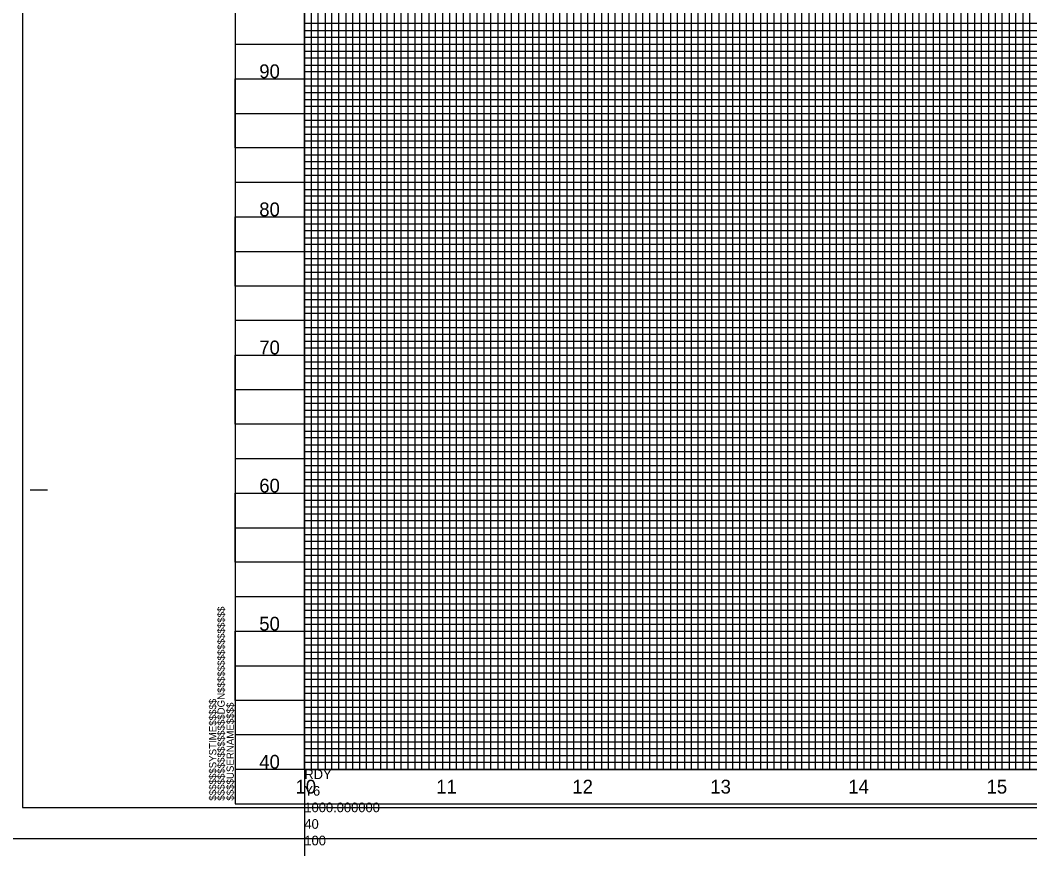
# Model space of a CAD drawing. Extents: x 2345490 to 2436403, y 465165 to 573888.
# Drawn here: x 2381561 to 2382292, y 548918 to 549518 of the extents above; entities that cross this region are included whole.
import ezdxf

# ---------------------------------------------------------------- set-up
doc = ezdxf.new("R2010")
doc.units = 0
for name, color, linetype in [('Old_Level_18', 7, 'Continuous'), ('Old_Level_40', 7, 'Continuous'), ('Old_Level_41', 7, 'Continuous'), ('Old_Level_42', 7, 'Continuous'), ('Old_Level_43', 7, 'Continuous'), ('Old_Level_50', 7, 'Continuous'), ('Old_Level_51', 7, 'Continuous'), ('Old_Level_52', 7, 'Continuous'), ('Old_Level_62', 7, 'Continuous'), ('Old_Level_63', 7, 'Continuous')]:
    doc.layers.add(name, color=color, linetype=linetype)

msp = doc.modelspace()

# ---------------------------------------------------------------- linework, layer by layer
at = {"layer": 'Old_Level_18'}
msp.add_line((2381716.79875, 548950.3665), (2381716.79875, 548950.3665), dxfattribs=at)
msp.add_line((2381716.79875, 548950.3665), (2381716.79875, 548950.3665), dxfattribs=at)
msp.add_lwpolyline([(2383216.79875, 550000.3665), (2381716.79875, 550000.3665), (2381716.79875, 548950.3665), (2383216.79875, 548950.3665)], close=True, dxfattribs=at)
at = {"layer": 'Old_Level_40'}
msp.add_line((2381716.79875, 548950.3665), (2381716.79875, 548950.3665), dxfattribs=at)
msp.add_line((2381716.79875, 548950.3665), (2381716.79875, 548950.3665), dxfattribs=at)
msp.add_line((2381716.79875, 548950.3665), (2381716.79875, 548950.3665), dxfattribs=at)
msp.add_line((2381716.79875, 548950.3665), (2381716.79875, 548950.3665), dxfattribs=at)
at = {"layer": 'Old_Level_41'}
for p, q in [((2381568.29875, 549177.8665), (2381580.79875, 549177.8665)), ((2383216.79875, 548975.3665), (2381716.79875, 548975.3665))]:
    msp.add_line(p, q, dxfattribs=at)
for points in [[(2381716.79875, 550000.3665), (2381766.79875, 550000.3665), (2381766.79875, 548975.3665), (2381816.79875, 548975.3665), (2381816.79875, 550000.3665), (2381866.79875, 550000.3665), (2381866.79875, 548975.3665), (2381916.79875, 548975.3665), (2381916.79875, 550000.3665), (2381966.79875, 550000.3665), (2381966.79875, 548975.3665), (2382016.79875, 548975.3665), (2382016.79875, 550000.3665), (2382066.79875, 550000.3665), (2382066.79875, 548975.3665), (2382116.79875, 548975.3665), (2382116.79875, 550000.3665), (2382166.79875, 550000.3665), (2382166.79875, 548975.3665), (2382216.79875, 548975.3665), (2382216.79875, 550000.3665), (2382266.79875, 550000.3665), (2382266.79875, 548975.3665), (2382316.79875, 548975.3665)], [(2381791.79875, 548975.3665), (2381791.79875, 550000.3665), (2381841.79875, 550000.3665), (2381841.79875, 548975.3665), (2381891.79875, 548975.3665), (2381891.79875, 550000.3665), (2381941.79875, 550000.3665), (2381941.79875, 548975.3665), (2381991.79875, 548975.3665), (2381991.79875, 550000.3665), (2382041.79875, 550000.3665), (2382041.79875, 548975.3665), (2382091.79875, 548975.3665), (2382091.79875, 550000.3665), (2382141.79875, 550000.3665), (2382141.79875, 548975.3665), (2382191.79875, 548975.3665), (2382191.79875, 550000.3665), (2382241.79875, 550000.3665), (2382241.79875, 548975.3665), (2382291.79875, 548975.3665), (2382291.79875, 550000.3665), (2382341.79875, 550000.3665)], [(2383216.79875, 549500.3665), (2381716.79875, 549500.3665), (2381716.79875, 549450.3665), (2383216.79875, 549450.3665)], [(2383216.79875, 549400.3665), (2381716.79875, 549400.3665), (2381716.79875, 549350.3665), (2383216.79875, 549350.3665)], [(2383216.79875, 549325.3665), (2381716.79875, 549325.3665), (2381716.79875, 549375.3665), (2383216.79875, 549375.3665)], [(2383216.79875, 549300.3665), (2381716.79875, 549300.3665), (2381716.79875, 549250.3665), (2383216.79875, 549250.3665)], [(2383216.79875, 549225.3665), (2381716.79875, 549225.3665), (2381716.79875, 549275.3665), (2383216.79875, 549275.3665)], [(2383216.79875, 549200.3665), (2381716.79875, 549200.3665), (2381716.79875, 549150.3665), (2383216.79875, 549150.3665)], [(2383216.79875, 549100.3665), (2381716.79875, 549100.3665), (2381716.79875, 549050.3665), (2383216.79875, 549050.3665)], [(2383216.79875, 549025.3665), (2381716.79875, 549025.3665), (2381716.79875, 549075.3665), (2383216.79875, 549075.3665)], [(2383216.79875, 549000.3665), (2381716.79875, 549000.3665)], [(2381754.29875, 548950.3665), (2381754.29875, 548950.3665)]]:
    msp.add_lwpolyline(points, dxfattribs=at)
at = {"layer": 'Old_Level_42'}
for points in [[(2383216.79875, 549425.3665), (2381716.79875, 549425.3665), (2381716.79875, 549475.3665), (2383216.79875, 549475.3665)], [(2383216.79875, 549125.3665), (2381716.79875, 549125.3665), (2381716.79875, 549175.3665), (2383216.79875, 549175.3665)]]:
    msp.add_lwpolyline(points, dxfattribs=at)
at = {"layer": 'Old_Level_43'}
for points in [[(2381771.79875, 550000.3665), (2381771.79875, 548975.3665), (2381776.79875, 548975.3665), (2381776.79875, 550000.3665)], [(2381781.79875, 550000.3665), (2381781.79875, 548975.3665), (2381786.79875, 548975.3665), (2381786.79875, 550000.3665)], [(2381796.79875, 550000.3665), (2381796.79875, 548975.3665), (2381801.79875, 548975.3665), (2381801.79875, 550000.3665)], [(2381806.79875, 550000.3665), (2381806.79875, 548975.3665), (2381811.79875, 548975.3665), (2381811.79875, 550000.3665)], [(2381821.79875, 550000.3665), (2381821.79875, 548975.3665), (2381826.79875, 548975.3665), (2381826.79875, 550000.3665)], [(2381831.79875, 550000.3665), (2381831.79875, 548975.3665), (2381836.79875, 548975.3665), (2381836.79875, 550000.3665)], [(2381846.79875, 550000.3665), (2381846.79875, 548975.3665), (2381851.79875, 548975.3665), (2381851.79875, 550000.3665)], [(2381856.79875, 550000.3665), (2381856.79875, 548975.3665), (2381861.79875, 548975.3665), (2381861.79875, 550000.3665)], [(2381871.79875, 550000.3665), (2381871.79875, 548975.3665), (2381876.79875, 548975.3665), (2381876.79875, 550000.3665)], [(2381881.79875, 550000.3665), (2381881.79875, 548975.3665), (2381886.79875, 548975.3665), (2381886.79875, 550000.3665)], [(2381896.79875, 550000.3665), (2381896.79875, 548975.3665), (2381901.79875, 548975.3665), (2381901.79875, 550000.3665)], [(2381906.79875, 550000.3665), (2381906.79875, 548975.3665), (2381911.79875, 548975.3665), (2381911.79875, 550000.3665)], [(2381921.79875, 550000.3665), (2381921.79875, 548975.3665), (2381926.79875, 548975.3665), (2381926.79875, 550000.3665)], [(2381931.79875, 548975.3665), (2381936.79875, 548975.3665), (2381936.79875, 550000.3665)], [(2381931.79875, 550000.3665), (2381931.79875, 548975.3665)], [(2381946.79875, 550000.3665), (2381946.79875, 548975.3665), (2381951.79875, 548975.3665), (2381951.79875, 550000.3665)], [(2381956.79875, 550000.3665), (2381956.79875, 548975.3665), (2381961.79875, 548975.3665), (2381961.79875, 550000.3665)], [(2381971.79875, 550000.3665), (2381971.79875, 548975.3665), (2381976.79875, 548975.3665), (2381976.79875, 550000.3665)], [(2381981.79875, 550000.3665), (2381981.79875, 548975.3665), (2381986.79875, 548975.3665), (2381986.79875, 550000.3665)], [(2381996.79875, 550000.3665), (2381996.79875, 548975.3665), (2382001.79875, 548975.3665), (2382001.79875, 550000.3665)], [(2382006.79875, 550000.3665), (2382006.79875, 548975.3665), (2382011.79875, 548975.3665), (2382011.79875, 550000.3665)], [(2382021.79875, 550000.3665), (2382021.79875, 548975.3665), (2382026.79875, 548975.3665), (2382026.79875, 550000.3665)], [(2382031.79875, 550000.3665), (2382031.79875, 548975.3665), (2382036.79875, 548975.3665), (2382036.79875, 550000.3665)], [(2382046.79875, 550000.3665), (2382046.79875, 548975.3665), (2382051.79875, 548975.3665), (2382051.79875, 550000.3665)], [(2382056.79875, 550000.3665), (2382056.79875, 548975.3665), (2382061.79875, 548975.3665), (2382061.79875, 550000.3665)], [(2382071.79875, 550000.3665), (2382071.79875, 548975.3665), (2382076.79875, 548975.3665), (2382076.79875, 550000.3665)], [(2382081.79875, 550000.3665), (2382081.79875, 548975.3665), (2382086.79875, 548975.3665), (2382086.79875, 550000.3665)], [(2382096.79875, 550000.3665), (2382096.79875, 548975.3665), (2382111.79875, 548975.3665), (2382111.79875, 550000.3665)], [(2382101.79875, 550000.3665), (2382101.79875, 548975.3665), (2382106.79875, 548975.3665), (2382106.79875, 550000.3665)], [(2382101.79875, 549999.7665), (2382101.79875, 548975.3665), (2382106.79875, 548975.3665), (2382106.79875, 549999.7665)], [(2382121.79875, 550000.3665), (2382121.79875, 548975.3665), (2382126.79875, 548975.3665), (2382126.79875, 550000.3665)], [(2382131.79875, 550000.3665), (2382131.79875, 548975.3665), (2382136.79875, 548975.3665), (2382136.79875, 550000.3665)], [(2382146.79875, 550000.3665), (2382146.79875, 548975.3665), (2382151.79875, 548975.3665), (2382151.79875, 550000.3665)], [(2382156.79875, 550000.3665), (2382156.79875, 548975.3665), (2382161.79875, 548975.3665), (2382161.79875, 550000.3665)], [(2382171.79875, 550000.3665), (2382171.79875, 548975.3665), (2382176.79875, 548975.3665), (2382176.79875, 550000.3665)], [(2382181.79875, 550000.3665), (2382181.79875, 548975.3665), (2382186.79875, 548975.3665), (2382186.79875, 550000.3665)], [(2382196.79875, 550000.3665), (2382196.79875, 548975.3665), (2382201.79875, 548975.3665), (2382201.79875, 550000.3665)], [(2382206.79875, 550000.3665), (2382206.79875, 548975.3665), (2382211.79875, 548975.3665), (2382211.79875, 550000.3665)], [(2382221.79875, 550000.3665), (2382221.79875, 548975.3665), (2382226.79875, 548975.3665), (2382226.79875, 550000.3665)], [(2382231.79875, 550000.3665), (2382231.79875, 548975.3665), (2382236.79875, 548975.3665), (2382236.79875, 550000.3665)], [(2382246.79875, 550000.3665), (2382246.79875, 548975.3665)], [(2382251.79875, 550000.3665), (2382251.79875, 548975.3665), (2382256.79875, 548975.3665), (2382256.79875, 550000.3665), (2382261.79875, 550000.3665), (2382261.79875, 548975.3665), (2382271.79875, 548975.3665), (2382271.79875, 550000.3665), (2382276.79875, 550000.3665), (2382276.79875, 548975.3665), (2382281.79875, 548975.3665), (2382281.79875, 550000.3665), (2382286.79875, 550000.3665), (2382286.79875, 548975.3665)], [(2383166.79875, 549515.3665), (2381766.79875, 549515.3665), (2381766.79875, 549510.3665), (2383166.79875, 549510.3665)], [(2383166.79875, 549505.3665), (2381766.79875, 549505.3665), (2381766.79875, 549495.3665), (2383166.79875, 549495.3665)], [(2383166.79875, 549490.3665), (2381766.79875, 549490.3665), (2381766.79875, 549485.3665), (2383166.79875, 549485.3665)], [(2383166.79875, 549480.3665), (2381766.79875, 549480.3665)], [(2381766.79875, 549470.3665), (2383166.79875, 549470.3665)], [(2383166.79875, 549465.3665), (2381766.79875, 549465.3665), (2381766.79875, 549460.3665), (2383166.79875, 549460.3665)], [(2383166.79875, 549455.3665), (2381766.79875, 549455.3665), (2381766.79875, 549445.3665), (2383166.79875, 549445.3665)], [(2383166.79875, 549440.3665), (2381766.79875, 549440.3665), (2381766.79875, 549435.3665), (2383166.79875, 549435.3665)], [(2383166.79875, 549430.3665), (2381766.79875, 549430.3665), (2381766.79875, 549420.3665), (2383166.79875, 549420.3665)], [(2383166.79875, 549415.3665), (2381766.79875, 549415.3665), (2381766.79875, 549410.3665), (2383166.79875, 549410.3665)], [(2383166.79875, 549405.3665), (2381766.79875, 549405.3665), (2381766.79875, 549395.3665), (2383166.79875, 549395.3665)], [(2383166.79875, 549390.3665), (2381766.79875, 549390.3665), (2381766.79875, 549385.3665), (2383166.79875, 549385.3665)], [(2383166.79875, 549380.3665), (2381766.79875, 549380.3665), (2381766.79875, 549370.3665), (2383166.79875, 549370.3665)], [(2383166.79875, 549365.3665), (2381766.79875, 549365.3665), (2381766.79875, 549360.3665), (2383166.79875, 549360.3665)], [(2383166.79875, 549355.3665), (2381766.79875, 549355.3665), (2381766.79875, 549345.3665), (2383166.79875, 549345.3665)], [(2383166.79875, 549340.3665), (2381766.79875, 549340.3665), (2381766.79875, 549335.3665), (2383166.79875, 549335.3665)], [(2383166.79875, 549330.3665), (2381766.79875, 549330.3665), (2381766.79875, 549320.3665), (2383166.79875, 549320.3665)], [(2383166.79875, 549315.3665), (2381766.79875, 549315.3665), (2381766.79875, 549310.3665), (2383166.79875, 549310.3665)], [(2383166.79875, 549305.3665), (2381766.79875, 549305.3665), (2381766.79875, 549295.3665), (2383166.79875, 549295.3665)], [(2383166.79875, 549290.3665), (2381766.79875, 549290.3665), (2381766.79875, 549285.3665), (2383166.79875, 549285.3665)], [(2383166.79875, 549280.3665), (2381766.79875, 549280.3665), (2381766.79875, 549270.3665), (2383166.79875, 549270.3665)], [(2383166.79875, 549265.3665), (2381766.79875, 549265.3665), (2381766.79875, 549260.3665), (2383166.79875, 549260.3665)], [(2383166.79875, 549255.3665), (2381766.79875, 549255.3665), (2381766.79875, 549245.3665), (2383166.79875, 549245.3665)], [(2383166.79875, 549240.3665), (2381766.79875, 549240.3665), (2381766.79875, 549235.3665), (2383166.79875, 549235.3665)], [(2383166.79875, 549230.3665), (2381766.79875, 549230.3665), (2381766.79875, 549220.3665), (2383166.79875, 549220.3665)], [(2383166.79875, 549215.3665), (2381766.79875, 549215.3665), (2381766.79875, 549210.3665), (2383166.79875, 549210.3665)], [(2383166.79875, 549205.3665), (2381766.79875, 549205.3665), (2381766.79875, 549195.3665), (2383166.79875, 549195.3665)], [(2383166.79875, 549190.3665), (2381766.79875, 549190.3665), (2381766.79875, 549185.3665), (2383166.79875, 549185.3665)], [(2383166.79875, 549180.3665), (2381766.79875, 549180.3665)], [(2381766.79875, 549170.3665), (2383166.79875, 549170.3665)], [(2383166.79875, 549165.3665), (2381766.79875, 549165.3665), (2381766.79875, 549160.3665), (2383166.79875, 549160.3665)], [(2383166.79875, 549155.3665), (2381766.79875, 549155.3665)], [(2381766.79875, 549145.3665), (2383166.79875, 549145.3665)], [(2383166.79875, 549140.3665), (2381766.79875, 549140.3665), (2381766.79875, 549135.3665), (2383166.79875, 549135.3665)], [(2383166.79875, 549130.3665), (2381766.79875, 549130.3665), (2381766.79875, 549120.3665), (2383166.79875, 549120.3665)], [(2383166.79875, 549115.3665), (2381766.79875, 549115.3665), (2381766.79875, 549110.3665), (2383166.79875, 549110.3665)], [(2383166.79875, 549105.3665), (2381766.79875, 549105.3665), (2381766.79875, 549095.3665), (2383166.79875, 549095.3665)], [(2383166.79875, 549090.3665), (2381766.79875, 549090.3665), (2381766.79875, 549085.3665), (2383166.79875, 549085.3665)], [(2383166.79875, 549080.3665), (2381766.79875, 549080.3665), (2381766.79875, 549070.3665), (2383166.79875, 549070.3665)], [(2383166.79875, 549065.3665), (2381766.79875, 549065.3665), (2381766.79875, 549060.3665), (2383166.79875, 549060.3665)], [(2383166.79875, 549055.3665), (2381766.79875, 549055.3665), (2381766.79875, 549045.3665), (2383166.79875, 549045.3665)], [(2383166.79875, 549040.3665), (2381766.79875, 549040.3665), (2381766.79875, 549035.3665), (2383166.79875, 549035.3665)], [(2383166.79875, 549030.3665), (2381766.79875, 549030.3665), (2381766.79875, 549020.3665), (2383166.79875, 549020.3665)], [(2383166.79875, 549015.3665), (2381766.79875, 549015.3665), (2381766.79875, 549010.3665), (2383166.79875, 549010.3665)], [(2383166.79875, 549005.3665), (2381766.79875, 549005.3665), (2381766.79875, 548995.3665), (2383166.79875, 548995.3665)], [(2383166.79875, 548990.3665), (2381766.79875, 548990.3665), (2381766.79875, 548985.3665), (2383166.79875, 548985.3665)], [(2383166.79875, 548980.3665), (2381766.79875, 548980.3665)]]:
    msp.add_lwpolyline(points, dxfattribs=at)
at = {"layer": 'Old_Level_50'}
msp.add_lwpolyline([(2383229.29875, 550002.9165), (2381562.79875, 550002.9165), (2381562.79875, 548947.8165), (2383229.29875, 548947.8165)], close=True, dxfattribs=at)
at = {"layer": 'Old_Level_51'}
msp.add_lwpolyline([(2383233.79875, 550025.3665), (2381549.79875, 550025.3665), (2381549.79875, 548925.3665), (2383233.79875, 548925.3665)], close=True, dxfattribs=at)
at = {"layer": 'Old_Level_52'}
msp.add_line((2381562.79875, 548947.8165), (2381562.79875, 548947.8165), dxfattribs=at)
at = {"layer": 'Old_Level_63'}
for q in [(2381766.79875, 551475.3665), (2384166.79875, 548975.3665), (2381766.79875, 546475.3665)]:
    msp.add_line((2381766.79875, 548975.3665), q, dxfattribs=at)

# ---------------------------------------------------------------- texts
at = {"layer": 'Old_Level_41'}
for s, p in [('$$$$$$$$$$$$$$$$DGN$$$$$$$$$$$$$$$$', (2381709.14875, 548952.729)), ('$$$$$$SYSTIME$$$$$', (2381703.09875, 548952.729)), ('$$$$USERNAME$$$$', (2381715.72375, 548952.7415))]:
    msp.add_text(s, height=5.25, rotation=90, dxfattribs=at).set_placement(p)
at = {"layer": 'Old_Level_62'}
for s, p in [('90', (2381734.1855, 549475.8665)), ('80', (2381734.1855, 549375.8665)), ('70', (2381734.1855, 549275.8665)), ('60', (2381734.1855, 549175.8665)), ('50', (2381734.1855, 549075.8665)), ('40', (2381734.1855, 548975.8665)), ('10', (2381760.3825, 548957.8665)), ('11', (2381862.222, 548957.8665)), ('12', (2381960.77025, 548957.8665)), ('13', (2382060.605, 548957.8665)), ('14', (2382160.4475, 548957.8665)), ('15', (2382260.54, 548957.8665))]:
    msp.add_text(s, height=10.000001, dxfattribs=at).set_placement(p)
at = {"layer": 'Old_Level_63'}
for s, height, p in [('RDY', 7.000001, (2381766.79875, 548968.3665)), ('Y6', 7.000001, (2381766.79875, 548956.36625)), ('1000.000000', 7.0000005, (2381766.79875, 548944.36625)), ('40', 7.000001, (2381766.79875, 548932.36625)), ('100', 7.000001, (2381766.79875, 548920.36625))]:
    msp.add_text(s, height=height, dxfattribs=at).set_placement(p)

doc.saveas('drawing.dxf')
